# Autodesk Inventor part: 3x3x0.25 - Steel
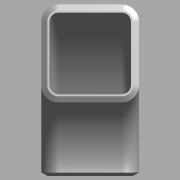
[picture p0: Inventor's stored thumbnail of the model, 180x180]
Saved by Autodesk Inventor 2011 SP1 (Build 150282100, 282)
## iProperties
Created: 2011-03
Part Number: 3x3x0.25 - Steel
Material: Default
Document SubType Name: Modeling
Designer: bamfomg
Density: 1 g/cm^3
Author: bamfomg
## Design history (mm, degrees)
derived "Square Tube Corners.ipt" dims "d2" = 38.1, "d3" = 38.1, "d6" = 6.35, "d7" = 6.35, "d8" = 6.35, "d12" = 90 deg, "d16" = 4.7625, "d18" = 30 deg, "ID_Rad" = 7.14375, "OD_Rad" = 13.49375, "Side_One" = 76.2, "Side_Two" = 76.2, "Thickness" = 6.35, "Bend_IDRad" = 57.15, "Bevel_Angl" = 30 deg, "Bevel_Dist" = 4.7625
body "Solid1"
feature "Solid1::Square Tube Corners.ipt" dims "d2" = 38.1, "d3" = 38.1, "d6" = 6.35, "d7" = 6.35, "d8" = 6.35, "d12" = 90 deg, "d16" = 4.7625, "d18" = 30 deg, "ID_Rad" = 7.14375, "OD_Rad" = 13.49375, "Side_One" = 76.2, "Side_Two" = 76.2, "Thickness" = 6.35, "Bend_IDRad" = 57.15, "Bevel_Angl" = 30 deg, "Bevel_Dist" = 4.7625, "ScaleForDerivedMember" = 10
tag "TaggingFeature1"
